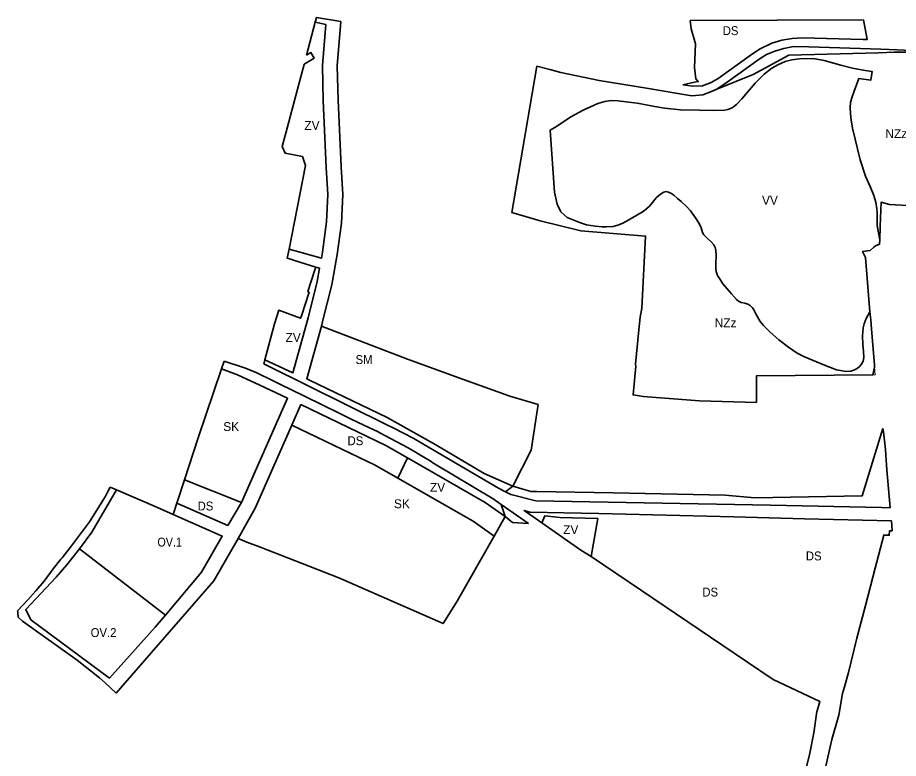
# Model space of a CAD drawing. Extents: x -650971 to -642489, y -1074311 to -1062745.
# Drawn here: x -646342 to -645155, y -1071722 to -1070723 of the extents above; entities that cross this region are included whole.
import ezdxf

# ---------------------------------------------------------------- set-up
doc = ezdxf.new("R2010")
doc.units = 0
doc.header["$LTSCALE"] = 4.8
for name, color, linetype, lineweight in [('11', 7, 'Continuous', 35), ('15', 7, 'Continuous', 35), ('18', 7, 'Continuous', 35), ('20', 7, 'Continuous', 35), ('24', 7, 'Continuous', 35), ('40', 7, 'Continuous', 35), ('42', 7, 'Continuous', 35), ('45', 7, 'Continuous', 35), ('46', 7, 'Continuous', 35), ('62', 7, 'Continuous', 35)]:
    doc.layers.add(name, color=color, linetype=linetype, lineweight=lineweight)

msp = doc.modelspace()

# ---------------------------------------------------------------- linework, layer by layer
at = {"layer": '11'}
for points in [[(-646258.487, -1071439.265), (-646241.68, -1071416.887), (-646208.577, -1071360.044)], [(-646208.577, -1071360.044), (-646153.5, -1071383.85), (-646132.229, -1071393.179)], [(-646132.229, -1071393.179), (-646066.165, -1071422.155), (-646094.063, -1071471.007), (-646142.584, -1071528.664), (-646258.487, -1071439.265), (-646142.584, -1071528.664)], [(-646142.584, -1071528.664), (-646156.471, -1071545.166), (-646217.978, -1071613.552), (-646324, -1071535), (-646330.914, -1071521.11), (-646289.976, -1071477.514), (-646275.615, -1071460.886), (-646258.487, -1071439.265)]]:
    msp.add_lwpolyline(points, dxfattribs=at)
at = {"layer": '15'}
msp.add_line((-646010.14, -1071190.08), (-646008.714, -1071184.746), dxfattribs=at)
for points in [[(-645976.17, -1071035.39), (-645932.635, -1071047.688), (-645931.24, -1071039.686), (-645925.626, -1070998.754), (-645923.919, -1070961.855), (-645926.084, -1070925.481), (-645930.036, -1070835.367), (-645931.369, -1070787.913), (-645926.784, -1070732.812), (-645940.955, -1070729.799), (-645939.27, -1070723.43), (-645906.373, -1070728.716)], [(-645906.373, -1070728.716), (-645911.345, -1070788.463), (-645910.048, -1070834.649), (-645906.11, -1070924.449), (-645903.891, -1070961.723), (-645905.69, -1071000.578), (-645911.474, -1071042.764), (-645918.57, -1071083.449), (-645930.943, -1071133.161), (-645932.502, -1071139.426)], [(-645940.25, -1071059.59), (-645968.97, -1071050.66), (-645973.77, -1071049.17), (-645978.58, -1071047.68), (-645976.17, -1071035.39)], [(-646008.714, -1071184.746), (-645970.966, -1071202.169), (-645950.283, -1071128.057), (-645938.15, -1071079.311), (-645934.978, -1071061.119), (-645940.25, -1071059.59)], [(-645932.502, -1071139.426), (-645952.419, -1071210.117), (-645948.761, -1071211.885), (-645844.079, -1071262.487), (-645778.69, -1071299.362), (-645713.428, -1071337.765), (-645674.947, -1071355.071), (-645684.785, -1071362.539)], [(-646040.084, -1071376.813), (-645978.403, -1071236.481), (-646015.387, -1071218.854), (-646045.462, -1071204.917), (-646067.097, -1071196.699), (-646063.59, -1071186.331)], [(-646063.59, -1071186.331), (-646035.06, -1071195.87), (-646019.41, -1071202.36), (-645997.62, -1071213.03), (-645989.7, -1071216.91), (-645955.342, -1071233.725), (-645907.62, -1071257.08), (-645893.41, -1071264.04), (-645875.48, -1071272.81), (-645856.26, -1071281.91), (-645854.1, -1071282.93), (-645839.37, -1071290.6), (-645815.65, -1071303.41), (-645784.92, -1071321.93), (-645782.32, -1071323.5), (-645701.44, -1071372.25), (-645690.677, -1071379.721), (-645685.098, -1071395.824)], [(-645684.785, -1071362.539), (-645694.15, -1071357.83), (-645795.97, -1071297.93), (-645808.13, -1071290.78), (-645835.76, -1071276.35), (-645843.45, -1071272.53), (-646004.65, -1071192.55), (-646010.14, -1071190.08)], [(-645816.714, -1071316.828), (-645846, -1071300), (-645960.34, -1071245.09), (-645972.422, -1071272.568)], [(-645972.422, -1071272.568), (-646021.674, -1071384.575), (-646044.949, -1071425.333)], [(-645685.098, -1071395.824), (-645712, -1071377), (-645816.714, -1071316.828)], [(-646209.322, -1071634.004), (-646223.928, -1071620.168), (-646231.43, -1071613.06), (-646261.46, -1071589.38), (-646335.3, -1071537.05), (-646340.93, -1071531.64), (-646341.66, -1071524.87), (-646341.88, -1071522.81), (-646327.97, -1071508.29), (-646317.52, -1071496.12), (-646306.14, -1071482.86), (-646293.87, -1071466.43), (-646283.52, -1071453.34), (-646281.99, -1071451.4), (-646269.2, -1071435.22), (-646245.1, -1071403.04), (-646223.77, -1071369.24), (-646220.61, -1071363.16), (-646217.049, -1071356.382), (-646208.577, -1071360.044)], [(-646208.577, -1071360.044), (-646241.68, -1071416.887), (-646258.487, -1071439.265)], [(-646142.584, -1071528.664), (-646094.063, -1071471.007), (-646066.165, -1071422.155), (-646132.229, -1071393.179), (-646127.301, -1071378.036)], [(-646127.301, -1071378.036), (-646058.719, -1071407.796), (-646040.084, -1071376.813)], [(-646044.949, -1071425.333), (-646077.593, -1071482.499), (-646197.398, -1071620.579), (-646209.322, -1071634.004)], [(-646258.487, -1071439.265), (-646275.615, -1071460.886), (-646289.976, -1071477.514), (-646330.914, -1071521.11), (-646324, -1071535), (-646217.978, -1071613.552), (-646156.471, -1071545.166), (-646142.584, -1071528.664)]]:
    msp.add_lwpolyline(points, dxfattribs=at)
at = {"layer": '18'}
for points in [[(-645674.947, -1071355.071), (-645713.428, -1071337.765), (-645778.69, -1071299.362), (-645844.079, -1071262.487), (-645948.761, -1071211.885), (-645952.419, -1071210.117), (-645932.502, -1071139.426)], [(-645932.502, -1071139.426), (-645816.47, -1071183.63), (-645741.09, -1071211.36), (-645678.86, -1071233.58), (-645640.737, -1071244.963), (-645650.09, -1071306.433), (-645674.947, -1071355.071)]]:
    msp.add_lwpolyline(points, dxfattribs=at)
at = {"layer": '20'}
for points in [[(-646117.031, -1071346.48), (-646098.66, -1071290.03), (-646067.097, -1071196.699)], [(-646067.097, -1071196.699), (-646045.462, -1071204.917), (-646015.387, -1071218.854), (-645978.403, -1071236.481), (-646040.084, -1071376.813), (-646117.031, -1071346.48)], [(-646044.949, -1071425.333), (-646021.674, -1071384.575), (-645972.422, -1071272.568)], [(-645972.422, -1071272.568), (-645859.986, -1071326.563), (-645829.706, -1071343.963)], [(-645829.706, -1071343.963), (-645728.105, -1071402.346), (-645699.825, -1071422.134)], [(-645699.825, -1071422.134), (-645749.631, -1071509.908), (-645768.62, -1071540.17), (-645909.13, -1071478.56), (-646015.966, -1071436.691), (-646019.66, -1071435.37), (-646030.8, -1071431.15), (-646044.949, -1071425.333)]]:
    msp.add_lwpolyline(points, dxfattribs=at)
at = {"layer": '24'}
for p, q in [((-645445.81, -1070814.06), (-645429.993, -1070810.647)), ((-645684.785, -1071362.539), (-645674.947, -1071355.071)), ((-645690.677, -1071379.721), (-645653.742, -1071405.36))]:
    msp.add_line(p, q, dxfattribs=at)
for points in [[(-645435.711, -1070727.497), (-645202.41, -1070726.571), (-645197.539, -1070753.128), (-645202.96, -1070752.89)], [(-645429.993, -1070810.647), (-645424.969, -1070809.563), (-645428.39, -1070806.09), (-645430, -1070790.68), (-645428.73, -1070758.67), (-645434.53, -1070738.77), (-645435.711, -1070727.497)], [(-645202.96, -1070752.89), (-645285.11, -1070750.69), (-645298.41, -1070751.48), (-645312.2, -1070753.77), (-645325.82, -1070757.94), (-645342.41, -1070765.76), (-645354.98, -1070774.28), (-645398.04, -1070805.44), (-645407.37, -1070810.95), (-645419.18, -1070815.44), (-645432.07, -1070816.05), (-645445.81, -1070814.06)], [(-645400.05, -1070819.84), (-645385.99, -1070810.35), (-645342.94, -1070779.31), (-645333.12, -1070773.33), (-645321.9, -1070768.47), (-645309.78, -1070764.88), (-645296.51, -1070762.52), (-645275.8, -1070762.66), (-645179.18, -1070765.86), (-645156.988, -1070766.884), (-645100.32, -1070769.5), (-645046.46, -1070771.98), (-645023.25, -1070772.62)], [(-645303, -1070774), (-645351, -1070800), (-645400.05, -1070819.84)], [(-645100.268, -1070771.946), (-645143, -1070770), (-645161, -1070770), (-645182, -1070771), (-645303, -1070774)], [(-645972.422, -1071272.568), (-645960.34, -1071245.09), (-645846, -1071300), (-645816.714, -1071316.828), (-645829.706, -1071343.963)], [(-645829.706, -1071343.963), (-645859.986, -1071326.563), (-645972.422, -1071272.568)], [(-645674.947, -1071355.071), (-645650.28, -1071362.07), (-645642.431, -1071362.259), (-645539.738, -1071364.092), (-645388.619, -1071366.991), (-645348.55, -1071370.559), (-645204.341, -1071368.19), (-645176.14, -1071277.26)], [(-645176.14, -1071277.26), (-645175.67, -1071279.45), (-645175.4, -1071281.93), (-645172.85, -1071305.45), (-645172.03, -1071312.96), (-645170.91, -1071332.86), (-645166.34, -1071384.07)], [(-646127.301, -1071378.036), (-646117.031, -1071346.48), (-646040.084, -1071376.813)], [(-645166.34, -1071384.07), (-645178.28, -1071383.61), (-645327.76, -1071380.76), (-645497.84, -1071377.53), (-645643.56, -1071374.75), (-645677.58, -1071366.16), (-645684.785, -1071362.539)], [(-646040.084, -1071376.813), (-646058.719, -1071407.796), (-646127.301, -1071378.036)], [(-645653.742, -1071405.36), (-645675.177, -1071403.922), (-645685.098, -1071395.824), (-645690.677, -1071379.721)], [(-645635.795, -1071404.403), (-645659.6, -1071387.71), (-645651.93, -1071389.82), (-645558.9, -1071391.8), (-645376.87, -1071396.41), (-645281.92, -1071398.82), (-645164.76, -1071401.79), (-645163.56, -1071415.3)], [(-645569.07, -1071449.88), (-645560.11, -1071398.7), (-645611.58, -1071397.14), (-645631.44, -1071394.9), (-645635.795, -1071404.403)], [(-645163.56, -1071415.3), (-645167.37, -1071415.2), (-645167.58, -1071421.19), (-645175.06, -1071420.93), (-645186.67, -1071465.55), (-645199.61, -1071515.68), (-645211.27, -1071560.01), (-645222.48, -1071606.08), (-645227.905, -1071625.277), (-645230.436, -1071634.261), (-645235.793, -1071663.703), (-645244.798, -1071696.585), (-645285.617, -1071875.733)], [(-645264.99, -1071658.731), (-645264.841, -1071657.687), (-645261.094, -1071645.025), (-645324.17, -1071615.53), (-645393.34, -1071568.75), (-645501.37, -1071495.68), (-645569.07, -1071449.88)], [(-645286.175, -1071761.228), (-645274.868, -1071717.176), (-645269.077, -1071687.396), (-645264.99, -1071658.731)]]:
    msp.add_lwpolyline(points, dxfattribs=at)
at = {"layer": '40'}
msp.add_line((-645829.706, -1071343.963), (-645816.714, -1071316.828), dxfattribs=at)
for points in [[(-645940.955, -1070729.799), (-645926.784, -1070732.812), (-645931.369, -1070787.913), (-645930.036, -1070835.367), (-645926.084, -1070925.481), (-645923.919, -1070961.855), (-645925.626, -1070998.754), (-645931.24, -1071039.686), (-645932.635, -1071047.688), (-645976.17, -1071035.39)], [(-645952.65, -1070773.98), (-645950.37, -1070765.38), (-645940.955, -1070729.799)], [(-645955.86, -1070786.21), (-645942.3, -1070777.96), (-645946.81, -1070770.47), (-645952.65, -1070773.98)], [(-645968.809, -1070835.035), (-645958.12, -1070794.72), (-645956, -1070786.73), (-645955.86, -1070786.21)], [(-645985.28, -1070897.13), (-645980.01, -1070877.28), (-645968.809, -1070835.035)], [(-645976.17, -1071035.39), (-645954.01, -1070922.8), (-645958.21, -1070910.84), (-645981.48, -1070906.35), (-645985.28, -1070897.13)], [(-646008.714, -1071184.746), (-645995.74, -1071136.22), (-645990.14, -1071117.76), (-645960.66, -1071128.71), (-645959.58, -1071125.39), (-645949.21, -1071093.62), (-645950.96, -1071092.8), (-645941.45, -1071063.3), (-645940.25, -1071059.59)], [(-645940.25, -1071059.59), (-645934.978, -1071061.119), (-645938.15, -1071079.311), (-645950.283, -1071128.057), (-645970.966, -1071202.169), (-646008.714, -1071184.746)], [(-645816.714, -1071316.828), (-645712, -1071377), (-645685.098, -1071395.824), (-645699.825, -1071422.134)], [(-645699.825, -1071422.134), (-645728.105, -1071402.346), (-645829.706, -1071343.963)], [(-645635.795, -1071404.403), (-645631.44, -1071394.9), (-645611.58, -1071397.14), (-645560.11, -1071398.7), (-645569.07, -1071449.88)], [(-645569.07, -1071449.88), (-645583.18, -1071441.3), (-645635.795, -1071404.403)]]:
    msp.add_lwpolyline(points, dxfattribs=at)
at = {"layer": '42', "lineweight": 13}
msp.add_lwpolyline([(-645189.902, -1071204.885), (-645187.466, -1071194.782), (-645186.64, -1071204.86)], close=True, dxfattribs=at)
at = {"layer": '45'}
for points in [[(-645367.028, -1071107.348), (-645370.698, -1071105.6), (-645373.291, -1071103.543), (-645380.193, -1071095.851), (-645391.902, -1071082.302), (-645395.222, -1071076.62), (-645398.979, -1071070.938), (-645400.796, -1071065.748), (-645401.408, -1071061.465), (-645401.233, -1071054.647), (-645400.796, -1071044.157), (-645401.408, -1071037.251), (-645402.194, -1071033.492), (-645404.172, -1071029.687), (-645407.492, -1071025.841), (-645412.735, -1071020.771), (-645417.453, -1071016.051), (-645419.026, -1071013.254), (-645421.21, -1071006.61), (-645423.648, -1071000.865), (-645428.541, -1070993.348), (-645435.443, -1070984.082), (-645441.361, -1070977.635), (-645448.001, -1070971.341), (-645452.982, -1070967.057), (-645457.875, -1070962.949), (-645462.069, -1070959.89), (-645464.865, -1070958.491), (-645468.185, -1070957.966), (-645471.418, -1070958.578), (-645474.301, -1070960.414), (-645477.971, -1070963.036), (-645481.466, -1070966.271), (-645486.534, -1070972.652), (-645490.641, -1070977.722), (-645494.223, -1070980.781), (-645499.204, -1070984.54), (-645521.535, -1070997.886), (-645527.302, -1071001.033), (-645533.156, -1071003.131), (-645539.622, -1071004.966), (-645548.534, -1071005.316), (-645554.524, -1071005.405), (-645563.698, -1071004.618), (-645575.406, -1071002.782), (-645583.707, -1071000.16), (-645601.41, -1070992.83), (-645610, -1070985), (-645615, -1070975), (-645618.798, -1070958.861), (-645624.321, -1070875.224), (-645615.817, -1070870.187), (-645596.689, -1070857.387), (-645579.841, -1070848.008), (-645560.079, -1070839.137), (-645550.832, -1070836.602), (-645542.642, -1070835.35), (-645533.268, -1070835.731), (-645507.299, -1070838.899), (-645483.61, -1070843.208), (-645470.235, -1070845.487), (-645448.7, -1070847.895), (-645423.364, -1070848.402), (-645404.15, -1070848.781), (-645389.329, -1070848.148), (-645385.148, -1070847.387), (-645379.448, -1070845.106), (-645373.241, -1070840.417), (-645366.02, -1070832.94), (-645348.318, -1070811.675), (-645336.046, -1070799.793), (-645325.785, -1070791.428), (-645317.677, -1070786.866), (-645307.923, -1070782.557), (-645298.731, -1070780.176), (-645288.343, -1070778.909), (-645279.349, -1070778.402), (-645267.315, -1070779.162), (-645255.407, -1070781.443), (-645233.003, -1070787.399), (-645217.086, -1070791.58), (-645200.111, -1070794.621), (-645190.59, -1070796.152), (-645192.298, -1070807.665), (-645208.696, -1070805.535), (-645215.063, -1070822.589), (-645217.778, -1070830.159), (-645219.787, -1070837.502), (-645220.312, -1070845.02), (-645219.351, -1070858.481), (-645216.991, -1070872.38), (-645206.872, -1070914.991), (-645199.714, -1070937.126), (-645193.51, -1070951.2), (-645188.377, -1070963.313), (-645185.843, -1070972.23), (-645184.357, -1070981.146), (-645183.833, -1070986.74), (-645183.746, -1071003.786), (-645182.261, -1071013.633), (-645180.506, -1071022.777)], [(-645180.506, -1071022.777), (-645180.506, -1071022.778), (-645180.72, -1071028.86), (-645186.18, -1071030.83), (-645188.39, -1071032.86), (-645193.24, -1071037.31), (-645203.66, -1071038.81), (-645199.57, -1071046.58), (-645193.592, -1071119.776)], [(-645193.592, -1071119.776), (-645193.872, -1071120.142), (-645198.678, -1071128.971), (-645201.648, -1071136.226), (-645202.951, -1071141.698), (-645203.738, -1071152.537), (-645203.301, -1071164.132), (-645202.34, -1071173.66), (-645201.903, -1071181.615), (-645202.777, -1071186.423), (-645205.049, -1071190.531), (-645207.575, -1071193.492), (-645211.07, -1071196.464), (-645215.351, -1071198.562), (-645219.283, -1071199.786), (-645225.487, -1071200.398), (-645238.506, -1071198.212), (-645254.845, -1071191.919), (-645281.707, -1071180.74), (-645291.581, -1071175.845), (-645303.551, -1071167.541), (-645316.308, -1071157.576), (-645328.059, -1071147.471), (-645336.884, -1071138.467), (-645341.689, -1071132.873), (-645345.097, -1071126.754), (-645347.631, -1071121.771), (-645349.99, -1071117.401), (-645352, -1071114.429), (-645354.883, -1071111.631), (-645358.203, -1071109.621), (-645362.223, -1071108.484), (-645367.028, -1071107.348)]]:
    msp.add_lwpolyline(points, dxfattribs=at)
at = {"layer": '46'}
for points in [[(-645400.05, -1070819.84), (-645351, -1070800), (-645303, -1070774)], [(-645303, -1070774), (-645182, -1070771), (-645161, -1070770), (-645143, -1070770), (-645100.268, -1070771.946)], [(-645180.506, -1071022.777), (-645182.261, -1071013.633), (-645183.746, -1071003.786), (-645183.833, -1070986.74), (-645184.357, -1070981.146), (-645185.843, -1070972.23), (-645188.377, -1070963.313), (-645193.51, -1070951.2), (-645199.714, -1070937.126), (-645206.872, -1070914.991), (-645216.991, -1070872.38), (-645219.351, -1070858.481), (-645220.312, -1070845.02), (-645219.787, -1070837.502), (-645217.778, -1070830.159), (-645215.063, -1070822.589), (-645208.696, -1070805.535), (-645192.298, -1070807.665), (-645190.59, -1070796.152), (-645200.111, -1070794.621), (-645217.086, -1070791.58), (-645233.003, -1070787.399), (-645255.407, -1070781.443), (-645267.315, -1070779.162), (-645279.349, -1070778.402), (-645288.343, -1070778.909), (-645298.731, -1070780.176), (-645307.923, -1070782.557), (-645317.677, -1070786.866), (-645325.785, -1070791.428), (-645336.046, -1070799.793), (-645348.318, -1070811.675), (-645366.02, -1070832.94), (-645373.241, -1070840.417), (-645379.448, -1070845.106), (-645385.148, -1070847.387), (-645389.329, -1070848.148), (-645404.15, -1070848.781), (-645423.364, -1070848.402), (-645448.7, -1070847.895), (-645470.235, -1070845.487), (-645483.61, -1070843.208), (-645507.299, -1070838.899), (-645533.268, -1070835.731), (-645542.642, -1070835.35), (-645550.832, -1070836.602), (-645560.079, -1070839.137), (-645579.841, -1070848.008), (-645596.689, -1070857.387), (-645615.817, -1070870.187), (-645624.321, -1070875.224), (-645618.798, -1070958.861), (-645615, -1070975), (-645610, -1070985), (-645601.41, -1070992.83), (-645583.707, -1071000.16), (-645575.406, -1071002.782), (-645563.698, -1071004.618), (-645554.524, -1071005.405), (-645548.534, -1071005.316), (-645539.622, -1071004.966), (-645533.156, -1071003.131), (-645527.302, -1071001.033), (-645521.535, -1070997.886), (-645499.204, -1070984.54), (-645494.223, -1070980.781), (-645490.641, -1070977.722), (-645486.534, -1070972.652), (-645481.466, -1070966.271), (-645477.971, -1070963.036), (-645474.301, -1070960.414), (-645471.418, -1070958.578), (-645468.185, -1070957.966), (-645464.865, -1070958.491), (-645462.069, -1070959.89), (-645457.875, -1070962.949), (-645452.982, -1070967.057), (-645448.001, -1070971.341), (-645441.361, -1070977.635), (-645435.443, -1070984.082), (-645428.541, -1070993.348), (-645423.648, -1071000.865), (-645421.21, -1071006.61), (-645419.026, -1071013.254), (-645417.453, -1071016.051), (-645412.735, -1071020.771), (-645407.492, -1071025.841), (-645404.172, -1071029.687), (-645402.194, -1071033.492), (-645401.408, -1071037.251), (-645400.796, -1071044.157), (-645401.233, -1071054.647), (-645401.408, -1071061.465), (-645400.796, -1071065.748), (-645398.979, -1071070.938), (-645395.222, -1071076.62), (-645391.902, -1071082.302), (-645380.193, -1071095.851), (-645373.291, -1071103.543), (-645370.698, -1071105.6), (-645367.028, -1071107.348)], [(-645583.18, -1071010.7), (-645637.94, -1070997.4), (-645676.292, -1070985.89), (-645642.52, -1070788.7)], [(-645642.52, -1070788.7), (-645625, -1070793.5), (-645610.25, -1070797.55), (-645558.3, -1070808), (-645494.82, -1070818.45), (-645452.31, -1070825.52), (-645433.49, -1070828.76), (-645418.67, -1070827.72), (-645409.52, -1070823.76), (-645400.05, -1070819.84)], [(-645134.973, -1070977.077), (-645167.47, -1070975.2), (-645178.73, -1070972.35), (-645179.87, -1071004.67), (-645180.506, -1071022.777)], [(-645504.79, -1071144.18), (-645503.08, -1071126.98), (-645500.94, -1071115.24), (-645495.87, -1071017.81), (-645583.18, -1071010.7)], [(-645367.028, -1071107.348), (-645362.223, -1071108.484), (-645358.203, -1071109.621), (-645354.883, -1071111.631), (-645352, -1071114.429), (-645349.99, -1071117.401), (-645347.631, -1071121.771), (-645345.097, -1071126.754), (-645341.689, -1071132.873), (-645336.884, -1071138.467), (-645328.059, -1071147.471), (-645316.308, -1071157.576), (-645303.551, -1071167.541), (-645291.581, -1071175.845), (-645281.707, -1071180.74), (-645254.845, -1071191.919), (-645238.506, -1071198.212), (-645225.487, -1071200.398), (-645219.283, -1071199.786), (-645215.351, -1071198.562), (-645211.07, -1071196.464), (-645207.575, -1071193.492), (-645205.049, -1071190.531), (-645202.777, -1071186.423), (-645201.903, -1071181.615), (-645202.34, -1071173.66), (-645203.301, -1071164.132), (-645203.738, -1071152.537), (-645202.951, -1071141.698), (-645201.648, -1071136.226), (-645198.678, -1071128.971), (-645193.872, -1071120.142), (-645193.592, -1071119.776)], [(-645193.592, -1071119.776), (-645192.68, -1071130.95), (-645191.72, -1071142.68), (-645187.72, -1071191.68), (-645187.466, -1071194.782), (-645189.902, -1071204.885)], [(-645189.902, -1071204.885), (-645346.31, -1071206.07), (-645346.67, -1071242.07), (-645423.08, -1071239.85), (-645499.36, -1071233.94), (-645512.84, -1071231.9), (-645509.22, -1071193.44), (-645509.49, -1071190.38), (-645504.79, -1071144.18)]]:
    msp.add_lwpolyline(points, dxfattribs=at)

# ---------------------------------------------------------------- texts
at = {"layer": '62'}
for s, width, p in [('DS', 0.95, (-645392, -1070747)), ('SM', 0.95, (-645886.606, -1071190.345)), ('DS', 0.95, (-645897.407, -1071299.717)), ('DS', 0.95, (-646099.407, -1071387.717)), ('OV.1', 0.9, (-646153.486, -1071436.306)), ('DS', 0.95, (-645279.957, -1071454.984)), ('DS', 0.95, (-645419.407, -1071503.717)), ('OV.2', 0.95, (-646243.486, -1071558.306))]:
    msp.add_text(s, height=12, dxfattribs=dict(at, width=width)).set_placement(p)
for s, p in [('ZV', (-645955.588, -1070874.768)), ('NZz', (-645172.866, -1070885.823)), ('VV', (-645339.075, -1070975.614)), ('NZz', (-645402.866, -1071140.823)), ('ZV', (-645980.931, -1071160.591)), ('SK', (-646064.883, -1071280.659)), ('ZV', (-645786.398, -1071362.507)), ('SK', (-645834.883, -1071384.659)), ('ZV', (-645606.931, -1071419.591))]:
    msp.add_text(s, height=12, dxfattribs=at).set_placement(p)

doc.saveas('drawing.dxf')
